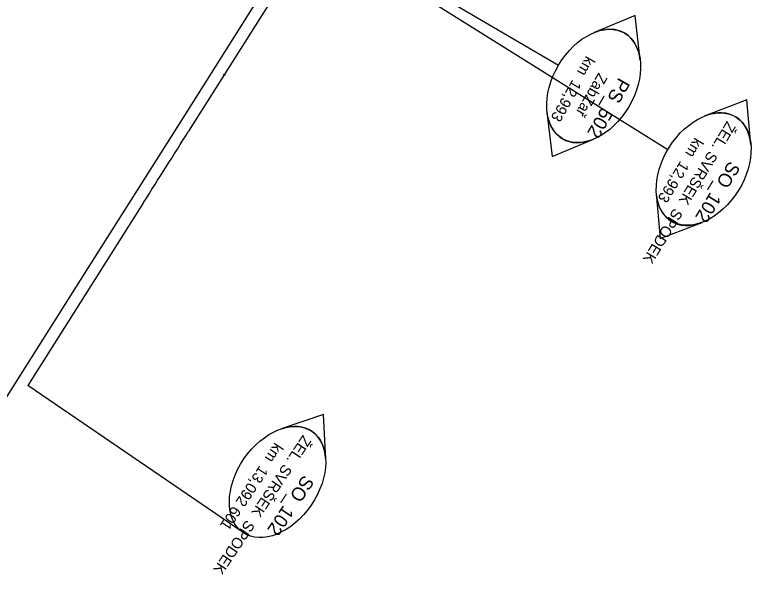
# Model space of a CAD drawing. Extents: x -743359 to -742769, y -1127804 to -1126284.
# Drawn here: x -743229.5 to -743093.1, y -1127220.5 to -1127113.5 of the extents above; entities that cross this region are included whole.
import ezdxf

# ---------------------------------------------------------------- set-up
doc = ezdxf.new("R2010")
doc.units = 0
for name, color, linetype in [('_Násyp', 7, 'Continuous'), ('_Zabezpečovací zařízení_trasa', 7, 'Continuous'), ('bublina_fialová_čára_tenká', 7, 'Continuous'), ('bublina_růžová_230_čára_tenká', 7, 'Continuous'), ('bublina_růžová_230_čára_tučná', 7, 'Continuous'), ('Default', 7, 'Continuous'), ('POP_OBLOUK', 7, 'Continuous'), ('SMER_VYS_VYROVNANI', 7, 'Continuous')]:
    doc.layers.add(name, color=color, linetype=linetype)

# ---------------------------------------------------------------- blocks, each defined once
blk = doc.blocks.new('AeccTickCircle')
at = {"layer": 'Default'}
blk.add_circle((0, 0), 5, dxfattribs=at)

msp = doc.modelspace()

# ---------------------------------------------------------------- linework, layer by layer
at = {"layer": '_Zabezpečovací zařízení_trasa'}
msp.add_lwpolyline([(-743098.65, -1126974.15), (-743125.94, -1127017.38), (-743152.6, -1127059.61), (-743175.02, -1127095.12), (-743199.16, -1127133.35), (-743215.97, -1127159.94), (-743232.82, -1127186.51), (-743247.46, -1127209.81), (-743254.52, -1127221.64), (-743261.3, -1127233.69), (-743264.16, -1127239.2), (-743264.86, -1127241.11), (-743267.34, -1127245.82), (-743268.29, -1127247.16), (-743271.71, -1127253.75), (-743281.12, -1127274.2), (-743291.92, -1127301.42), (-743296.72, -1127315.22), (-743301.12, -1127329.13), (-743306.79, -1127349.51), (-743311.54, -1127370.06), (-743315.69, -1127392.87), (-743318.79, -1127415.84)], dxfattribs=at)
at = {"layer": 'bublina_fialová_čára_tenká'}
for p, q in [((-743129.51, -1127122.8), (-743175.48, -1127095.85)), ((-743109.42, -1127138.31), (-743174.12, -1127097.81))]:
    msp.add_line(p, q, dxfattribs=at)
at = {"layer": 'bublina_růžová_230_čára_tenká'}
msp.add_line((-743187.51, -1127208.64), (-743227.07, -1127181.59), dxfattribs=at)
at = {"layer": 'bublina_růžová_230_čára_tučná'}
for p, q in [((-743115.4, -1127113.65), (-743123.03, -1127116.79)), ((-743115.4, -1127113.65), (-743123.03, -1127116.79)), ((-743114.46, -1127121.85), (-743115.4, -1127113.65)), ((-743114.46, -1127121.85), (-743115.4, -1127113.65)), ((-743094.84, -1127129.14), (-743102.55, -1127132.08)), ((-743094.84, -1127129.14), (-743102.55, -1127132.08)), ((-743094.11, -1127137.36), (-743094.84, -1127129.14)), ((-743094.11, -1127137.36), (-743094.84, -1127129.14)), ((-743131.63, -1127131.3), (-743130.69, -1127139.51)), ((-743131.63, -1127131.3), (-743130.69, -1127139.51)), ((-743130.69, -1127139.51), (-743123.06, -1127136.36)), ((-743130.69, -1127139.51), (-743123.06, -1127136.36)), ((-743111.53, -1127146.36), (-743110.8, -1127154.58)), ((-743111.53, -1127146.36), (-743110.8, -1127154.58)), ((-743110.8, -1127154.58), (-743103.09, -1127151.64)), ((-743110.8, -1127154.58), (-743103.09, -1127151.64)), ((-743172.69, -1127186.98), (-743180.52, -1127189.6)), ((-743172.69, -1127186.98), (-743180.52, -1127189.6)), ((-743172.3, -1127195.22), (-743172.69, -1127186.98)), ((-743172.3, -1127195.22), (-743172.69, -1127186.98))]:
    msp.add_line(p, q, dxfattribs=at)
for centre, major_axis in [((-743123.03, -1127126.57), (-5.72, -9.69)), ((-743102.8, -1127141.85), (-5.97, -9.53)), ((-743181.16, -1127199.36), (-6.35, -9.29))]:
    msp.add_ellipse(centre, major_axis=major_axis, ratio=0.666667, dxfattribs=at)
for centre, major_axis in [((-743123.03, -1127126.57), (5.72, 9.69)), ((-743123.07, -1127126.59), (-5.72, -9.69)), ((-743102.8, -1127141.85), (5.97, 9.54)), ((-743102.84, -1127141.87), (-5.97, -9.54)), ((-743181.16, -1127199.36), (6.35, 9.29))]:
    msp.add_ellipse(centre, major_axis=major_axis, ratio=0.666473, start_param=5.557317, end_param=7.009053, dxfattribs=at)
at = {"layer": 'SMER_VYS_VYROVNANI'}
for points in [[(-743178.71, -1127105.09), (-743197.53, -1127134.89)], [(-743205.82, -1127148.01), (-743227.07, -1127181.59)]]:
    msp.add_lwpolyline(points, dxfattribs=at)
msp.add_arc((-755881.53, -1119127.65), 15000, 327.677064, 327.736346, dxfattribs=at)

# ---------------------------------------------------------------- block references
at = {"layer": 'POP_OBLOUK', "xscale": 0.024999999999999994, "yscale": 0.024999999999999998, "rotation": 57.71650678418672}
msp.add_blockref('AeccTickCircle', (-743190.97, -1127124.5), dxfattribs=at)

# ---------------------------------------------------------------- texts
at = {"layer": '_Násyp'}
for s, height, rotation, p in [('km  12,993', 2, 240.1217, (-743124.39, -1127120.92)), ('ZabZař', 2, 240.1217, (-743122.12, -1127124.02)), ('PS_502', 2.5, 240.1217, (-743118.38, -1127124.89)), ('ŽEL. SVRŠEK  SPODEK', 2, 238.6088, (-743098.49, -1127132.92)), ('km  12,993', 2, 238.6088, (-743104.43, -1127135.92)), ('SO_102', 2.5, 238.6088, (-743098.07, -1127140.22)), ('ŽEL. SVRŠEK  SPODEK', 2, 236.3041, (-743176.49, -1127190.61)), ('km  13,092 601', 2, 236.3041, (-743181.63, -1127192)), ('SO_102', 2.5, 236.3041, (-743176.36, -1127197.92))]:
    msp.add_text(s, height=height, rotation=rotation, dxfattribs=at).set_placement(p)

doc.saveas('drawing.dxf')
